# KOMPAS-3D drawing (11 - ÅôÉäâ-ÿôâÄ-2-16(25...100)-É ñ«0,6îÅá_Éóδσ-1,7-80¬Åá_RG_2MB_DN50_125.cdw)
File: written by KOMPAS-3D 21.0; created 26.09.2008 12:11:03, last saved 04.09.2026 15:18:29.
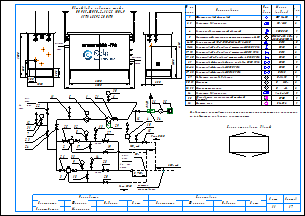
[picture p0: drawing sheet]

Sheets 1-2: A3, landscape

Document properties: Наименование: Макро:21; Автор: RaskoAdmin; Форматы листов документа: 2xA3; Полное имя файла: \\ur38nt01\Departments\КТО\КБ ПУРДГ\Заявки\Прайс-лист на типовые шкафы ГРПШ\ПУРДГ_стандарт_30_04_2026\ПУРДГ с RG_2MB\ПУРДГ-ШУГО-2-16(25...100)-Р до0,6МПа_Рвых-1,7-80кПа_RG_2MB_DN50_125.cdw

Title block, sheet 1: Наименование: Пункт учета газа / ПУГ-Ш-400-Р / ЛГТИ.485922.001ТУ; designation: ЛГТИ.03.4411141; sheet number: 1; Количество листов документа: 2; organisation: ООО "ЭЛЬСТЕР Газэлектроника"; Форматы листов документа: A3; stored path: C:\Рабочие документы\Компас\ПУГ\Схема.cdw; Разработал: Устинов; Проверил: Кошкин; Утвердил: Кошкин
Title block, sheet 2: sheet number: 2; stored path: D:\Рабочие документы\Заявки\ПУРДГ\ПУРДГ-ШУЭО-2-100-Р 4411220.cdw; designation, second copy: ЛГТИ.03.4411141-

Views: Вид 1, Вид 2
Referenced files: wcvoit.frw
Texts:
  Normal
  Общий вид и габариты шкафа
  ПУРДГ-ШУГО-2-16(25...100)-Р
  DN125
  Выход газа
  DN50
  Вход газа
  logo-rasko-ge.png
  DN 1
  местное
  сопротивление
  Римп DN20
  Выход
  газа
  Р=     кПа
  Вход
  Р=       МПа
  PDI
  № на
  схеме
  Усл.
  обозн.
  Марка
  (модель)
  Кол.
  Фильтр газовый фланцевый
  ФГ 16-50
  Регулятор давления газа
  RG/2MB
  Клапан предохранительный сбросной
  КПС DN20
  Измерительный комплекс с ротационным счетчиком Ду50
  СГ-ЭК-Р-(0,2...2,0)-
  Кран кнопочный VE-РАСКО-НЗ-1,6-G1/2-М20
  DN15
  Кран шаровой "под приварку" штуцерный DN20 PN16
  DN20
  Кран шаровой "под приварку" штуцерный DN15 PN16
  Кран шаровой "под приварку" штуцерный п/п DN20 PN16
  Кран шаровой фланцевый с мех. приводом DN50 PN16
  Кран шаровой фланцевый DN50 PN16
  Кран шаровой фланцевый DN125 PN16
  Индикатор перепада давления
  Манометр
  Манометр-напоромер
  Обогреватель газогорелочный шкафной
  (Эльтон")
  Счетчик газа
  Delta 15
  0...     МПа
  0...     кПа
  Venio-A-15
  ОГШН
  BK-G1,6
  Схема открывания дверей
  Предприятие изготовитель может заменять комплектующие на аналогичные,
  не ухудшающие заявленных характеристик.
  Должность
  Конструктор
  Фамилия
  Подпись
  Дата
  Согласовано
  Максимкин
  Лист
  Листов
  POLYLINE_STYLE_0.18_RGB_0_0_0
  POLYLINE_STYLE_0.50_RGB_0_0_0
  POLYLINE_STYLE_0.34_RGB_0_0_0
  PHANTOM_RGB_0_0_0_SC_1_THICK_0.18
  K5LT_THIN_RGB_0_0_0_THICK_0.18
  K5LT32769_RGB_0_0_0_THICK_0.18
  K5LT12_RGB_0_0_0_SC_1_THICK_0.18
  K5LT_DASHED_RGB_0_0_0_SC_1_THICK_0.18
  ACISOTGL_RGB_0_0_0_SC_0.8_THICK_0.25
  CONTINUOUS_RGB_0_127_31_THICK_0.3
  CONTINUOUS_RGB_0_0_255_THICK_0.35
  CONTINUOUS_RGB_255_0_0_THICK_0.35
  POLYLINE_STYLE_0.25_RGB_0_0_0
  CONTINUOUS_RGB_0_0_0_THICK_0.5
  POLYLINE_STYLE_0.35_RGB_0_0_255
  CONTINUOUS_RGB_0_0_0_THICK_0.4
  CONTINUOUS_RGB_0_0_0_THICK_0.35
  НЕВИДИМАЯ_RGB_0_0_0_SC_0.3_THICK_0.25
  СONTINUOUS_RGB_0_0_0_THICK_0.25
  ОСЕВАЯ2_RGB_248_153_30_SC_0.3_THICK_0.25
  Без оформления
Dimensions and other numbers on the sheet: 1; 1500; 250; 300; 1050; 550; 305; 2500; 4130; 2000; 2800; 5,,,7DN 1; 7; 31; 12; 22; 23; 24; 11; 5; 21; 6; 30; 25; 32; 8; 2; 17; 13; 27; 19; 4; 10; 15; 26; 33; 9; 3; 18; 14; 28; 20; 29; 2, 3; 6-10; 11-16; 17, 18; 19, 20; 22-26; 27, 28; 30, 31; 32, 33; 34; 35; 36; 16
